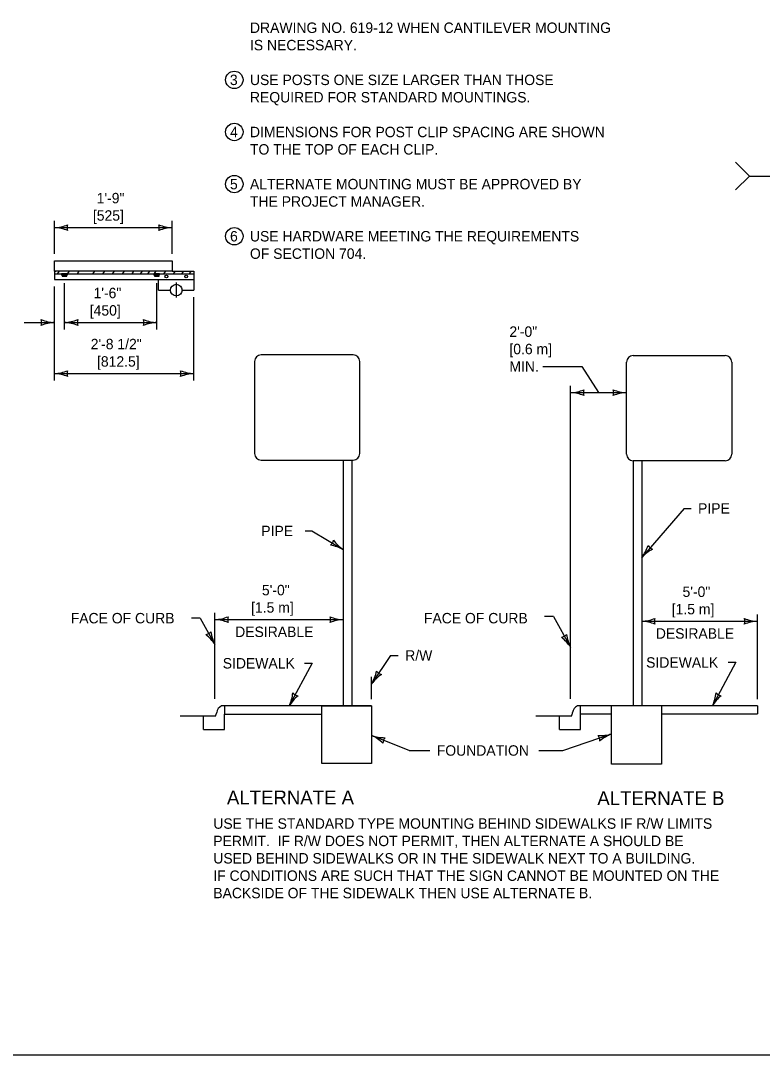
# Model space of a CAD drawing. Extents: x 49991.4 to 50021, y 49987.6 to 50011.4.
# Drawn here: x 50008.76 to 50013.03, y 49987.8 to 49993.75 of the extents above; entities that cross this region are included whole.
import ezdxf

# ---------------------------------------------------------------- set-up
doc = ezdxf.new("R2010")
doc.units = 0
for name, color, linetype in [('Level 1', 7, 'Continuous'), ('Level 2', 7, 'Continuous'), ('Level 3', 7, 'Continuous'), ('Level 5', 7, 'Continuous')]:
    doc.layers.add(name, color=color, linetype=linetype)

msp = doc.modelspace()

# ---------------------------------------------------------------- linework, layer by layer
at = {"layer": 'Level 1'}
for p, q in [((50008.9538, 49992.312), (50008.9626, 49992.312)), ((50008.9538, 49992.312), (50008.9538, 49992.2635)), ((50008.9719, 49992.2953), (50008.9832, 49992.312)), ((50009.0288, 49992.2953), (50009.0401, 49992.312)), ((50009.0856, 49992.2953), (50009.0969, 49992.312)), ((50009.1745, 49992.2953), (50009.1857, 49992.3118)), ((50009.2316, 49992.2953), (50009.2429, 49992.312)), ((50009.2885, 49992.2953), (50009.2998, 49992.312)), ((50009.3453, 49992.2953), (50009.3567, 49992.312)), ((50009.4003, 49992.2953), (50009.4115, 49992.312)), ((50009.4483, 49992.2953), (50009.4596, 49992.312)), ((50009.4913, 49992.2953), (50009.5027, 49992.312)), ((50009.5272, 49992.2953), (50009.5385, 49992.312)), ((50009.584, 49992.2953), (50009.5953, 49992.312)), ((50009.6307, 49992.312), (50009.7554, 49992.312)), ((50009.639, 49992.2953), (50009.6503, 49992.312)), ((50009.687, 49992.2953), (50009.6983, 49992.312)), ((50009.7301, 49992.2953), (50009.7414, 49992.312)), ((50009.7554, 49992.312), (50009.7554, 49992.2022)), ((50008.9538, 49992.2953), (50009.7554, 49992.2953)), ((50008.9538, 49992.2635), (50009.5527, 49992.2635)), ((50008.9979, 49992.2843), (50008.9979, 49992.2906)), ((50009.0005, 49992.2817), (50009.0231, 49992.2817)), ((50009.0071, 49992.2842), (50009.0071, 49992.2906)), ((50009.0163, 49992.2842), (50009.0163, 49992.2906)), ((50009.0256, 49992.2843), (50009.0256, 49992.2906)), ((50009.5289, 49992.2843), (50009.5289, 49992.2906)), ((50009.5315, 49992.2817), (50009.5541, 49992.2817)), ((50009.5381, 49992.2842), (50009.5381, 49992.2906)), ((50009.5473, 49992.2842), (50009.5473, 49992.2906)), ((50009.5527, 49992.2022), (50009.5527, 49992.2635)), ((50009.5527, 49992.2635), (50009.6868, 49992.2635)), ((50009.5566, 49992.2843), (50009.5566, 49992.2906)), ((50009.6868, 49992.2635), (50009.7545, 49992.2635)), ((50009.5527, 49992.2022), (50009.6217, 49992.2022)), ((50009.6882, 49992.2022), (50009.7554, 49992.2022)), ((50010.6728, 49991.8294), (50010.1429, 49991.8294)), ((50010.105, 49991.7916), (50010.105, 49991.2617)), ((50010.7107, 49991.2617), (50010.7107, 49991.7916)), ((50012.2457, 49991.2579), (50012.2457, 49991.7878)), ((50012.2836, 49991.8257), (50012.8135, 49991.8257)), ((50012.8513, 49991.7878), (50012.8513, 49991.2579)), ((50010.1429, 49991.2238), (50010.6728, 49991.2238)), ((50010.6161, 49991.2238), (50010.6161, 49989.809)), ((50010.6659, 49991.2238), (50010.6659, 49989.809)), ((50012.2836, 49991.22), (50012.2835, 49989.809)), ((50012.8135, 49991.22), (50012.2836, 49991.22)), ((50012.3334, 49991.22), (50012.3334, 49989.809)), ((50010.7791, 49989.809), (50009.9151, 49989.809)), ((50012.9996, 49989.809), (50011.9631, 49989.809)), ((50011.9808, 49989.7631), (50011.9808, 49989.809)), ((50012.1593, 49989.4734), (50012.1593, 49989.809)), ((50012.4465, 49989.809), (50012.4465, 49989.4734)), ((50012.9996, 49989.809), (50012.9996, 49989.7631)), ((50009.8775, 49989.7498), (50009.6775, 49989.7498)), ((50009.8112, 49989.6736), (50009.8112, 49989.7498)), ((50009.9329, 49989.6736), (50009.9322, 49989.7627)), ((50011.924, 49989.7497), (50011.724, 49989.7497)), ((50011.8591, 49989.6737), (50011.8591, 49989.7497)), ((50011.9808, 49989.6737), (50011.9808, 49989.7631)), ((50011.9808, 49989.7631), (50012.1593, 49989.7631)), ((50012.4465, 49989.7631), (50012.9996, 49989.7631)), ((50009.8112, 49989.6736), (50009.9329, 49989.6736)), ((50011.8591, 49989.6737), (50011.9808, 49989.6737)), ((50012.4465, 49989.4734), (50012.1593, 49989.4734))]:
    msp.add_line(p, q, dxfattribs=at)
for points in [[(49999.3835, 49998.9992), (50016.7501, 49998.9992), (50016.7501, 49987.7988), (49999.3835, 49987.7988)], [(50009.6307, 49992.3716), (50009.6307, 49992.312), (50008.9538, 49992.312), (50008.9538, 49992.3716)], [(50008.9952, 49992.2953), (50008.9952, 49992.2906), (50009.028, 49992.2906), (50009.028, 49992.2953)], [(50009.5262, 49992.2953), (50009.5262, 49992.2906), (50009.559, 49992.2906), (50009.559, 49992.2953)], [(50009.9322, 49989.809), (50009.9322, 49989.7627), (50010.492, 49989.7627), (50010.492, 49989.809)], [(50010.7791, 49989.809), (50010.7791, 49989.478), (50010.492, 49989.478), (50010.492, 49989.809)]]:
    msp.add_lwpolyline(points, close=True, dxfattribs=at)
for centre, radius in [((50009.598, 49992.2806), 0.00843), ((50009.7119, 49992.2806), 0.00843), ((50009.655, 49992.2022), 0.0333)]:
    msp.add_circle(centre, radius, dxfattribs=at)
for centre, radius, start, end in [((50009.0005, 49992.2842), 0.00257, 180, 270), ((50009.0046, 49992.2842), 0.00257, 270, 0), ((50009.0097, 49992.2842), 0.00257, 180, 270), ((50009.0138, 49992.2842), 0.00257, 270, 0), ((50009.0189, 49992.2842), 0.00257, 180, 270), ((50009.023, 49992.2842), 0.00257, 270, 0), ((50009.5315, 49992.2842), 0.00257, 180, 270), ((50009.5356, 49992.2842), 0.00257, 270, 0), ((50009.5407, 49992.2842), 0.00257, 180, 270), ((50009.5448, 49992.2842), 0.00257, 270, 0), ((50009.5499, 49992.2842), 0.00257, 180, 270), ((50009.554, 49992.2842), 0.00257, 270, 0), ((50010.1429, 49991.7916), 0.0379, 90, 180), ((50010.6728, 49991.7916), 0.0379, 0, 90), ((50012.2836, 49991.7878), 0.0379, 90, 180), ((50012.8135, 49991.7878), 0.0379, 0, 90), ((50010.1429, 49991.2617), 0.0379, 180, 270), ((50010.6728, 49991.2617), 0.0379, 270, 360), ((50012.2836, 49991.2579), 0.0379, 180, 270), ((50012.8135, 49991.2579), 0.0379, 270, 0), ((50009.9329, 49989.7669), 0.0457, 112.85095, 174.08821), ((50011.9809, 49989.7669), 0.0457, 112.88545, 174.08821), ((50009.842, 49989.7764), 0.0457, 326.7145, 354.08821), ((50011.8899, 49989.7764), 0.0457, 326.7145, 354.05141)]:
    msp.add_arc(centre, radius, start, end, dxfattribs=at)
for points in [[(50009.8802, 49989.7513), (50009.8791, 49989.7506), (50009.878, 49989.75), (50009.8775, 49989.7498)], [(50011.9281, 49989.7513), (50011.9271, 49989.7506), (50011.9259, 49989.75), (50011.924, 49989.7497)]]:
    msp.add_spline(points, degree=3, dxfattribs=at)
at = {"layer": 'Level 2'}
for centre in [(50009.9888, 49993.4121), (50009.9888, 49993.1121), (50009.9888, 49992.8121), (50009.9888, 49992.5121)]:
    msp.add_circle(centre, 0.05, dxfattribs=at)
at = {"layer": 'Level 3'}
for p, q in [((50012.8728, 49992.9388), (50012.9528, 49992.8588)), ((50012.8728, 49992.7788), (50012.9528, 49992.8588)), ((50012.9528, 49992.8588), (50014.1183, 49992.8588)), ((50008.9538, 49992.4116), (50008.9538, 49992.6016)), ((50008.9538, 49992.5616), (50009.6307, 49992.5616)), ((50009.6307, 49992.4116), (50009.6307, 49992.6016)), ((50008.9538, 49991.6817), (50008.9538, 49992.2235)), ((50009.0116, 49991.9755), (50009.0116, 49992.2417)), ((50009.5428, 49991.9755), (50009.5428, 49992.2417)), ((50009.7554, 49991.6817), (50009.7554, 49992.1622)), ((50008.7804, 49992.0155), (50008.9538, 49992.0155)), ((50009.0116, 49992.0155), (50009.5428, 49992.0155)), ((50008.9538, 49991.7217), (50009.7554, 49991.7217)), ((50011.7643, 49991.7632), (50011.9882, 49991.7632)), ((50011.9882, 49991.7632), (50012.0849, 49991.6121)), ((50011.924, 49989.8497), (50011.924, 49991.6521)), ((50011.924, 49991.6121), (50012.2457, 49991.6121)), ((50012.5782, 49990.9458), (50012.3334, 49990.6642)), ((50012.5782, 49990.9458), (50012.6171, 49990.9458)), ((50010.3964, 49990.8163), (50010.4357, 49990.8163)), ((50010.4357, 49990.8163), (50010.6161, 49990.7094)), ((50009.8775, 49989.8498), (50009.8775, 49990.3459)), ((50009.7927, 49990.3144), (50009.7419, 49990.3144)), ((50009.7927, 49990.3144), (50009.8775, 49990.1623)), ((50009.8775, 49990.3059), (50010.6161, 49990.3059)), ((50011.8252, 49990.3238), (50011.7744, 49990.3238)), ((50011.8252, 49990.3238), (50011.924, 49990.1466)), ((50012.3334, 49990.2963), (50012.9996, 49990.2963)), ((50012.9996, 49989.849), (50012.9996, 49990.3363)), ((50010.4376, 49990.0559), (50010.3044, 49989.809)), ((50010.3919, 49990.0559), (50010.4376, 49990.0559)), ((50010.8866, 49990.1), (50010.7791, 49989.9364)), ((50010.8866, 49990.1), (50010.9322, 49990.1)), ((50012.8753, 49990.0607), (50012.7395, 49989.809)), ((50012.8296, 49990.0607), (50012.8753, 49990.0607)), ((50010.7791, 49989.849), (50010.7791, 49989.9764)), ((50010.9951, 49989.5529), (50010.7791, 49989.6393)), ((50011.8796, 49989.5529), (50012.1593, 49989.6478)), ((50010.9951, 49989.5529), (50011.1138, 49989.5529)), ((50011.7411, 49989.5529), (50011.8796, 49989.5529))]:
    msp.add_line(p, q, dxfattribs=at)
for centre, radius, start, end in [((50008.9423, 49992.7943), 0.233, 272.82731, 292.07716), ((50008.9447, 49992.3394), 0.2223, 67.45601, 87.63952), ((50009.082, 49992.5616), 0.0548, 162.13882, 197.86118), ((50009.6399, 49992.7837), 0.2223, 247.45601, 267.63952), ((50009.5025, 49992.5616), 0.0548, 342.13882, 17.86118), ((50009.6422, 49992.3288), 0.233, 92.82731, 112.07716), ((50008.963, 49992.2376), 0.2223, 247.45601, 267.63952), ((50008.8256, 49992.0155), 0.0548, 342.13882, 17.86118), ((50008.9653, 49991.7828), 0.233, 92.82731, 112.07716), ((50009.0001, 49992.2482), 0.233, 272.82731, 292.07716), ((50009.0025, 49991.7934), 0.2223, 67.45601, 87.63952), ((50009.1398, 49992.0155), 0.0548, 162.13882, 197.86118), ((50009.552, 49992.2376), 0.2223, 247.45601, 267.63952), ((50009.4146, 49992.0155), 0.0548, 342.13882, 17.86118), ((50009.5543, 49991.7828), 0.233, 92.82731, 112.07716), ((50008.9423, 49991.9545), 0.233, 272.82731, 292.07716), ((50008.9447, 49991.4996), 0.2223, 67.45601, 87.63952), ((50009.082, 49991.7217), 0.0548, 162.13882, 197.86118), ((50009.7646, 49991.9439), 0.2223, 247.45601, 267.63952), ((50009.6272, 49991.7217), 0.0548, 342.13882, 17.86118), ((50009.7669, 49991.489), 0.233, 92.82731, 112.07716), ((50011.9125, 49991.8448), 0.233, 272.82731, 292.07716), ((50011.9148, 49991.39), 0.2223, 67.45601, 87.63952), ((50012.0522, 49991.6121), 0.0548, 162.13882, 197.86118), ((50012.2549, 49991.8342), 0.2223, 247.45601, 267.63952), ((50012.1175, 49991.6121), 0.0548, 342.13882, 17.86118), ((50012.2572, 49991.3794), 0.233, 92.82731, 112.07716), ((50010.5058, 49990.7747), 0.0548, 311.47918, 347.20154), ((50010.7373, 49990.8958), 0.2223, 216.79638, 236.97988), ((50010.5073, 49990.5033), 0.233, 62.16768, 81.41752), ((50012.1502, 49990.8082), 0.233, 321.82629, 341.07614), ((50012.495, 49990.5116), 0.2223, 116.45499, 136.63849), ((50012.4175, 49990.761), 0.0548, 211.13779, 246.86016), ((50009.866, 49990.5386), 0.233, 272.82731, 292.07716), ((50009.8683, 49990.0838), 0.2223, 67.45601, 87.63952), ((50010.0057, 49990.3059), 0.0548, 162.13882, 197.86118), ((50010.6253, 49990.528), 0.2223, 247.45601, 267.63952), ((50010.4879, 49990.3059), 0.0548, 342.13882, 17.86118), ((50010.6276, 49990.0732), 0.233, 92.82731, 112.07716), ((50012.3219, 49990.529), 0.233, 272.82731, 292.07716), ((50012.3242, 49990.0742), 0.2223, 67.45601, 87.63952), ((50012.4616, 49990.2963), 0.0548, 162.13882, 197.86118), ((50013.0088, 49990.5184), 0.2223, 247.45601, 267.63952), ((50012.8714, 49990.2963), 0.0548, 342.13882, 17.86118), ((50013.0111, 49990.0636), 0.233, 92.82731, 112.07716), ((50009.8134, 49990.2733), 0.0548, 282.13634, 317.8587), ((50010.0745, 49990.2654), 0.2223, 187.45353, 207.63704), ((50009.6817, 49990.036), 0.233, 32.82483, 52.07468), ((50011.8599, 49990.2577), 0.0548, 282.13634, 317.8587), ((50011.7282, 49990.0203), 0.233, 32.82483, 52.07468), ((50012.1209, 49990.2498), 0.2223, 187.45353, 207.63704), ((50010.5783, 49990.0546), 0.233, 329.51373, 348.76358), ((50010.9597, 49989.8068), 0.2223, 124.14243, 144.32594), ((50010.8495, 49990.0436), 0.0548, 218.82524, 254.5476), ((50010.0942, 49989.9094), 0.233, 334.48778, 353.73763), ((50010.4956, 49989.6955), 0.2223, 129.11648, 149.29998), ((50010.3653, 49989.9218), 0.0548, 223.79928, 259.52164), ((50012.5293, 49989.9094), 0.233, 334.48778, 353.73763), ((50012.9307, 49989.6955), 0.2223, 129.11648, 149.29998), ((50012.8004, 49989.9218), 0.0548, 223.79928, 259.52164), ((50010.6881, 49989.4365), 0.2223, 45.6546, 65.83811), ((50010.8549, 49989.8596), 0.233, 251.0259, 270.27575), ((50010.8981, 49989.5917), 0.0548, 140.33741, 176.05977), ((50012.0966, 49989.8611), 0.2223, 266.20475, 286.38826), ((50012.0379, 49989.6066), 0.0548, 0.88756, 36.60992), ((50012.245, 49989.4312), 0.233, 111.57605, 130.8259)]:
    msp.add_arc(centre, radius, start, end, dxfattribs=at)
at = {"layer": 'Level 5'}
msp.add_line((50009.6549, 49992.2455), (50009.6549, 49992.159), dxfattribs=at)

# ---------------------------------------------------------------- texts
at = {"layer": 'Level 2'}
for s, height, p in [('DRAWING NO. 619-12 WHEN CANTILEVER MOUNTING', 0.06, (50010.0788, 49993.6821)), ('IS NECESSARY.  ', 0.06, (50010.0788, 49993.5821)), ('3', 0.06, (50009.9636, 49993.3821)), ('USE POSTS ONE SIZE LARGER THAN THOSE', 0.06, (50010.0788, 49993.3821)), ('REQUIRED FOR STANDARD MOUNTINGS.  ', 0.06, (50010.0788, 49993.2821)), ('4', 0.06, (50009.9648, 49993.0821)), ('DIMENSIONS FOR POST CLIP SPACING ARE SHOWN', 0.06, (50010.0788, 49993.0821)), ('TO THE TOP OF EACH CLIP.', 0.06, (50010.0788, 49992.9821)), ('5', 0.06, (50009.9639, 49992.7821)), ('ALTERNATE MOUNTING MUST BE APPROVED BY', 0.06, (50010.0788, 49992.7821)), ('1\'-9"', 0.06, (50009.1969, 49992.7016)), ('THE PROJECT MANAGER.', 0.06, (50010.0788, 49992.6821)), ('[525]', 0.06, (50009.1751, 49992.6016)), ('6', 0.06, (50009.9643, 49992.4821)), ('USE HARDWARE MEETING THE REQUIREMENTS', 0.06, (50010.0788, 49992.4821)), ('OF SECTION 704. ', 0.06, (50010.0788, 49992.3821)), ('1\'-6"', 0.06, (50009.1788, 49992.1555)), ('[450]', 0.06, (50009.157, 49992.0555)), ('2\'-0"', 0.06, (50011.5717, 49991.9332)), ('2\'-8 1/2"', 0.06, (50009.1625, 49991.8617)), ('[0.6 m]', 0.06, (50011.5717, 49991.8332)), ('[812.5]', 0.06, (50009.1987, 49991.7617)), ('MIN.', 0.06, (50011.5717, 49991.7332)), ('PIPE', 0.06, (50012.6571, 49990.9158)), ('PIPE', 0.06, (50010.144, 49990.7863)), ('5\'-0"', 0.06, (50010.1477, 49990.4459)), ('5\'-0"', 0.06, (50012.568, 49990.4363)), ('[1.5 m]', 0.06, (50010.0854, 49990.3459)), ('FACE OF CURB', 0.06, (50009.0475, 49990.2844)), ('FACE OF CURB', 0.06, (50011.0799, 49990.2844)), ('[1.5 m]', 0.06, (50012.5058, 49990.3363)), ('DESIRABLE', 0.06, (50009.9936, 49990.2059)), ('DESIRABLE', 0.06, (50012.4142, 49990.1963)), ('R/W', 0.06, (50010.9722, 49990.07)), ('SIDEWALK', 0.06, (50009.9221, 49990.0247)), ('SIDEWALK', 0.06, (50012.3586, 49990.0295)), ('FOUNDATION', 0.06, (50011.1538, 49989.5229)), ('ALTERNATE A', 0.08, (50009.9464, 49989.2425)), ('ALTERNATE B', 0.08, (50012.0778, 49989.2387)), ('USE THE STANDARD TYPE MOUNTING BEHIND SIDEWALKS IF R/W LIMITS', 0.06, (50009.8679, 49989.1025)), ('PERMIT.  IF R/W DOES NOT PERMIT, THEN ALTERNATE A SHOULD BE', 0.06, (50009.8679, 49989.0025)), ('USED BEHIND SIDEWALKS OR IN THE SIDEWALK NEXT TO A BUILDING.', 0.06, (50009.8679, 49988.9025)), ('IF CONDITIONS ARE SUCH THAT THE SIGN CANNOT BE MOUNTED ON THE', 0.06, (50009.8679, 49988.8025)), ('BACKSIDE OF THE SIDEWALK THEN USE ALTERNATE B.', 0.06, (50009.8679, 49988.7025))]:
    msp.add_text(s, height=height, dxfattribs=at).set_placement(p)

doc.saveas('drawing.dxf')
